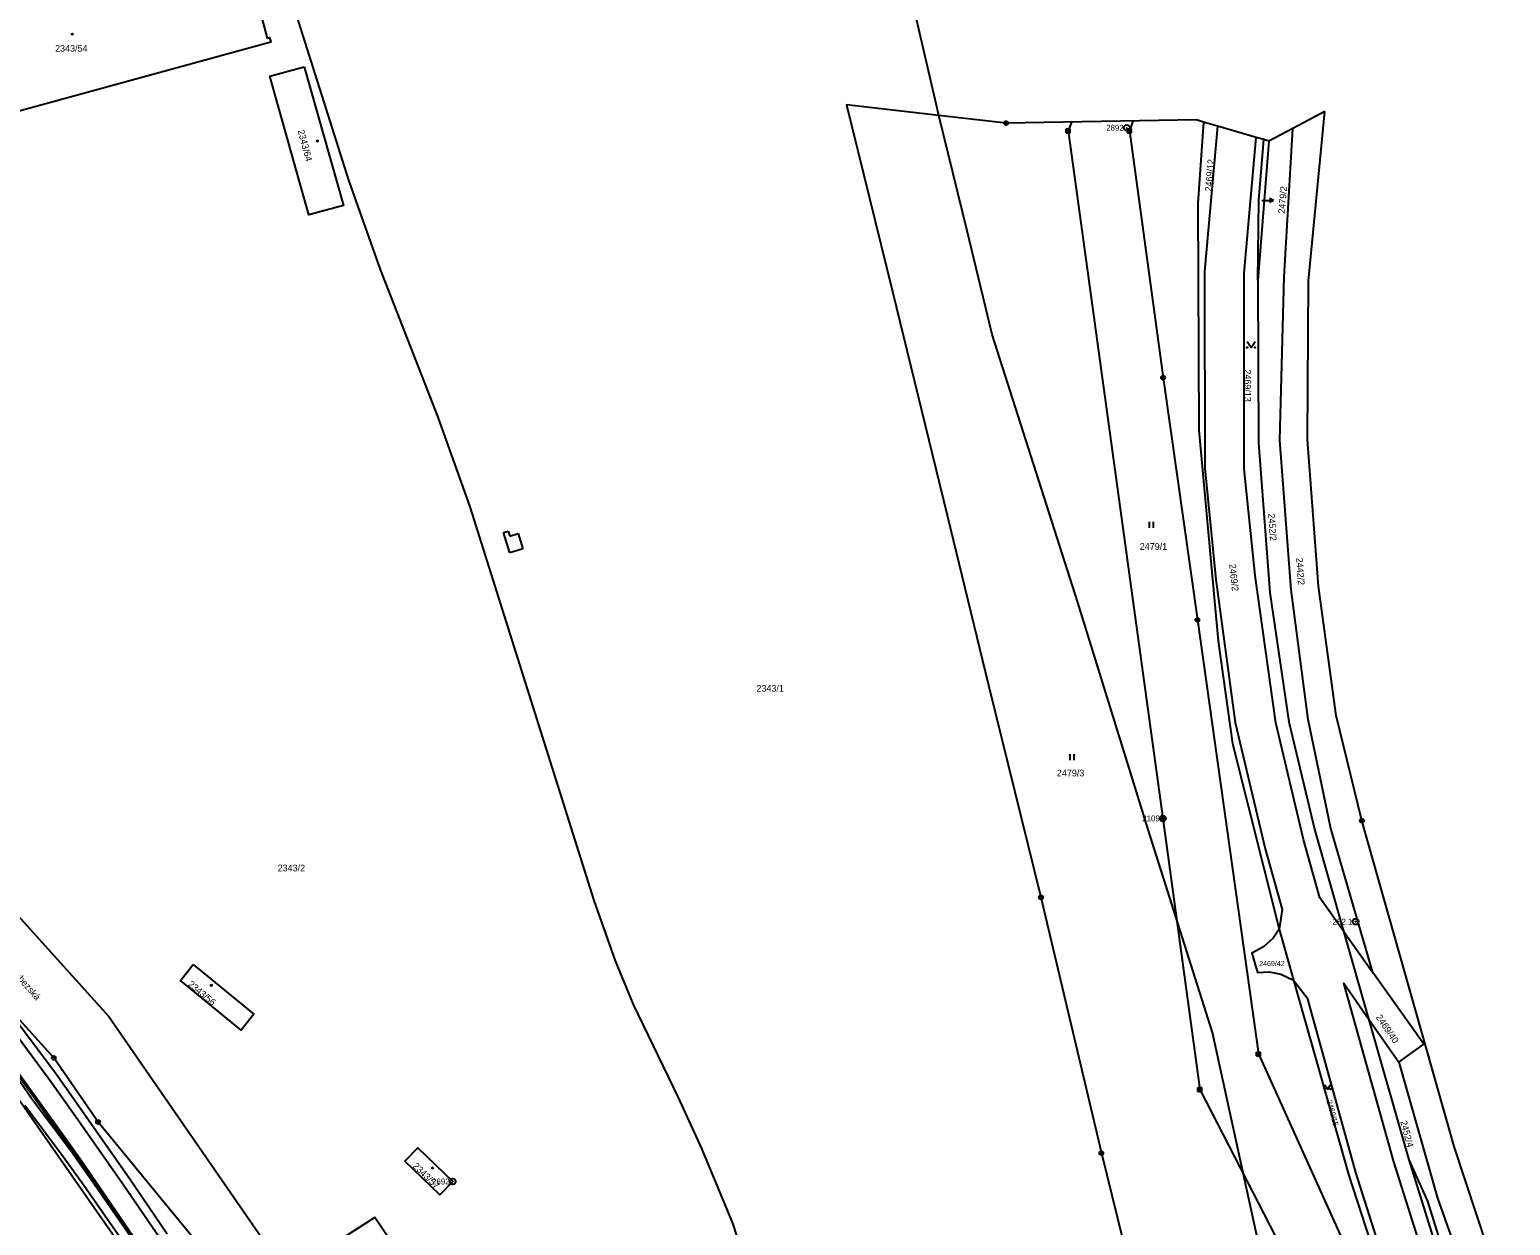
# Model space of a CAD drawing. Extents: x -821458 to -820266, y -1071458 to -1069826.
# Drawn here: x -820951.1 to -820575.5, y -1070854 to -1070550.7 of the extents above; entities that cross this region are included whole.
import ezdxf

# ---------------------------------------------------------------- set-up
doc = ezdxf.new("R2010")
doc.units = 0
for name, color, linetype in [('Vrstva 1', 7, 'Continuous'), ('Vrstva 13', 7, 'Continuous'), ('Vrstva 2', 7, 'Continuous'), ('Vrstva 3', 7, 'Continuous'), ('Vrstva 4', 7, 'Continuous'), ('Vrstva 5', 7, 'Continuous'), ('Vrstva 6', 7, 'Continuous'), ('Vrstva 7', 7, 'Continuous'), ('Vrstva 8', 7, 'Continuous')]:
    doc.layers.add(name, color=color, linetype=linetype)

msp = doc.modelspace()

# ---------------------------------------------------------------- linework, layer by layer
at = {"layer": 'Vrstva 1'}
for p, q in [((-820721.42, -1070568.42), (-820751, -1070439.83)), ((-820720.44, -1070572.46), (-820721.42, -1070568.42)), ((-820622.5, -1070571.49), (-820630.65, -1070575.77)), ((-820703.4, -1070574.43), (-820720.44, -1070572.46)), ((-820655.09, -1070573.64), (-820703.4, -1070574.43)), ((-820653.29, -1070574.2), (-820655.09, -1070573.64)), ((-820649.79, -1070575.18), (-820653.29, -1070574.2)), ((-820639.94, -1070578.04), (-820649.79, -1070575.18)), ((-820637.98, -1070578.61), (-820639.94, -1070578.04)), ((-820636.74, -1070578.97), (-820639.52, -1070614.28)), ((-820636.74, -1070578.97), (-820637.98, -1070578.61)), ((-820630.65, -1070575.77), (-820636.74, -1070578.97)), ((-820633.34, -1070773.88), (-820634.1, -1070778.9)), ((-820634.1, -1070778.9), (-820630.5, -1070791.8)), ((-820617.78, -1070779.43), (-820610.37, -1070789.85)), ((-820617.78, -1070779.43), (-820611.45, -1070801.61)), ((-820630.5, -1070791.8), (-820627.05, -1070796.31)), ((-820969.81, -1070799.27), (-820928.15, -1070858.94)), ((-820611.45, -1070801.61), (-820603.74, -1070812.61)), ((-820611.45, -1070801.61), (-820601.24, -1070837.38))]:
    msp.add_line(p, q, dxfattribs=at)
for points in [[(-820757.14, -1070921.43), (-820751.69, -1070918.45), (-820772.76, -1070853.45), (-820780.56, -1070834.55), (-820786.59, -1070821.38), (-820797.89, -1070798.01), (-820802.49, -1070786.9), (-820807.86, -1070771.6), (-820839.34, -1070671.73), (-820847.49, -1070649.05), (-820862.12, -1070611.55), (-820870.18, -1070588.9), (-820893.88, -1070513.71)], [(-820987.3, -1070553.53), (-820984.32, -1070553.15), (-820984.15, -1070553.64), (-820896.5, -1070529.65), (-820896.17, -1070530.88), (-820896.75, -1070531.03), (-820895.04, -1070537.38), (-820894.46, -1070537.22), (-820894.09, -1070538.61), (-820894.67, -1070538.77), (-820892.95, -1070545.12), (-820892.38, -1070544.96), (-820892, -1070546.35), (-820892.58, -1070546.51), (-820890.86, -1070552.89), (-820890.28, -1070552.73), (-820889.96, -1070553.93), (-820980.44, -1070578.68)], [(-820881.48, -1070560.15), (-820871.53, -1070595.32), (-820880.27, -1070597.68), (-820890.22, -1070562.51), (-820881.48, -1070560.15)], [(-820720.44, -1070572.46), (-820743.88, -1070569.76), (-820732.22, -1070617.16), (-820718.37, -1070673.87), (-820707.85, -1070716.96), (-820694.56, -1070770.81), (-820679.24, -1070835.68), (-820666.97, -1070885.51), (-820662.98, -1070891.79), (-820644.73, -1070894.66)], [(-820575.47, -1070877.31), (-820589.75, -1070833.98), (-820613.15, -1070751.36), (-820619.68, -1070724.73), (-820624.16, -1070691.86), (-820626.98, -1070654.7), (-820626.67, -1070614.41), (-820622.5, -1070571.49)], [(-820638.63, -1070895.3), (-820639, -1070860.06), (-820651.05, -1070805.08), (-820667.4, -1070753.6), (-820685.24, -1070696.04), (-820706.9, -1070628.02), (-820713.28, -1070601.74), (-820720.44, -1070572.46)], [(-820653.29, -1070574.2), (-820654.8, -1070594.7), (-820654.5, -1070652.3), (-820649.6, -1070705.8), (-820646, -1070731.8), (-820634.1, -1070778.9)], [(-820649.79, -1070575.18), (-820653.1, -1070612.1), (-820653, -1070661.95), (-820650.17, -1070690.23), (-820645.27, -1070726.49), (-820637.71, -1070758.5), (-820633.34, -1070773.88)], [(-820617.78, -1070779.43), (-820623.84, -1070770.91), (-820627.97, -1070756.18), (-820634.95, -1070726.51), (-820640.2, -1070689.19), (-820643, -1070662.1), (-820643, -1070612.5), (-820639.94, -1070578.04)], [(-820639.52, -1070614.28), (-820639.3, -1070594), (-820637.98, -1070578.61)], [(-820610.37, -1070789.85), (-820621.01, -1070753.33), (-820626.77, -1070725.67), (-820631.06, -1070692.78), (-820633.95, -1070654.83), (-820632.82, -1070613.38), (-820630.65, -1070575.77)], [(-821122.14, -1070589.18), (-821105.63, -1070607.47), (-821052.06, -1070666.88), (-820984.98, -1070741.28), (-820930.99, -1070801.01), (-820892.18, -1070857.22), (-820885.9, -1070866.32)], [(-820639.52, -1070614.28), (-820639.34, -1070655.55), (-820636.46, -1070693.5), (-820631.68, -1070726.33), (-820625.08, -1070753.87), (-820617.78, -1070779.43)], [(-820830.48, -1070974.59), (-820860.94, -1070928.75), (-820897.16, -1070874.24), (-820903.48, -1070864.73), (-820933.76, -1070827.81), (-820944.98, -1070811.53), (-820977.14, -1070776.05), (-821034.82, -1070708.07), (-821038.73, -1070703.46), (-821059.1, -1070680.77), (-821064.12, -1070689.43)], [(-820634.1, -1070778.9), (-820635.67, -1070781.21), (-820638.11, -1070783.39)], [(-820638.11, -1070783.39), (-820641.03, -1070784.97), (-820639.65, -1070789.87), (-820636.63, -1070789.7)], [(-820909.62, -1070787.86), (-820894.2, -1070800.43), (-820897.46, -1070804.5), (-820912.83, -1070791.87), (-820909.62, -1070787.86)], [(-820636.63, -1070789.7), (-820633.7, -1070790.28), (-820630.5, -1070791.8)], [(-820630.5, -1070791.8), (-820616.42, -1070841.34), (-820608.96, -1070864.52)], [(-820591.18, -1070881.76), (-820605.01, -1070837.88), (-820617.76, -1070792.61), (-820611.45, -1070801.61)], [(-820603.74, -1070812.61), (-820597.44, -1070808.04), (-820610.37, -1070789.85)], [(-820627.05, -1070796.31), (-820614.77, -1070840.62), (-820600.74, -1070884.82), (-820599.23, -1070892.6)], [(-820603.74, -1070812.61), (-820594, -1070847.1), (-820579.4, -1070888.1)], [(-820855.92, -1070837.73), (-820852.62, -1070834.37), (-820843.79, -1070842.89), (-820847.05, -1070846.25), (-820855.92, -1070837.73)], [(-820601.24, -1070837.38), (-820587.25, -1070882.1), (-820583.95, -1070890.7)], [(-820847.86, -1070875.03), (-820857.84, -1070860.4), (-820863.58, -1070851.99), (-820885.4, -1070866), (-820885.9, -1070866.32)]]:
    msp.add_lwpolyline(points, dxfattribs=at)
at = {"layer": 'Vrstva 13'}
msp.add_lwpolyline([(-820904.89, -1070889.85), (-820906.75, -1070887.02), (-820915.84, -1070872.29), (-820921.1, -1070864.54), (-820924.16, -1070858.76), (-820935.49, -1070842.47), (-820940.7, -1070835.15), (-820950.45, -1070822.13), (-820960.57, -1070807.59), (-820967.99, -1070796.51), (-820968.45, -1070795.86), (-820964.16, -1070792.35), (-820957.12, -1070802.08), (-820946.13, -1070816.91), (-820939.51, -1070826.31), (-820927.43, -1070843.51), (-820917.95, -1070857.45), (-820910.17, -1070868.83), (-820902.77, -1070879.51), (-820898.51, -1070886.1), (-820899.32, -1070886.63)], close=True, dxfattribs=at)
for points in [[(-820916.21, -1070856.27), (-820925.69, -1070842.31), (-820937.79, -1070825.09), (-820944.42, -1070815.67), (-820955.42, -1070800.84)], [(-820924.84, -1070856.86), (-820937.9, -1070837.8), (-820944.15, -1070829.04), (-820956.36, -1070812.01)], [(-820956.64, -1070812.21), (-820944.43, -1070829.24), (-820938.14, -1070838.08), (-820925.14, -1070857.05)], [(-820952.33, -1070823.49), (-820942.57, -1070836.51), (-820937.39, -1070843.81), (-820926.14, -1070859.96), (-820923.08, -1070865.74), (-820917.78, -1070873.55), (-820908.71, -1070888.26), (-820906.28, -1070891.93), (-820900.9, -1070899.97), (-820897.17, -1070905.83), (-820879.17, -1070932.66), (-820864.17, -1070956.47), (-820859.08, -1070965.49), (-820854.56, -1070972.59), (-820849.07, -1070982.53), (-820847.11, -1070985.26), (-820846.8, -1070985.75)]]:
    msp.add_lwpolyline(points, dxfattribs=at)
at = {"layer": 'Vrstva 3'}
for p, q in [((-820667.01, -1070677.1), (-820667.01, -1070675.6)), ((-820666.01, -1070677.1), (-820666.01, -1070675.6)), ((-820687.12, -1070736), (-820687.12, -1070734.5)), ((-820686.12, -1070736), (-820686.12, -1070734.5))]:
    msp.add_line(p, q, dxfattribs=at)
for points in [[(-820642.25, -1070629.85), (-820641.25, -1070631.35), (-820640.25, -1070629.85)], [(-820622.5, -1070818.41), (-820621.8, -1070819.46), (-820621.1, -1070818.41)]]:
    msp.add_lwpolyline(points, dxfattribs=at)
for centre, radius in [((-820642.25, -1070631.35), 0.1), ((-820640.25, -1070631.35), 0.1), ((-820622.5, -1070819.46), 0.07), ((-820621.1, -1070819.46), 0.07)]:
    msp.add_circle(centre, radius, dxfattribs=at)
at = {"layer": 'Vrstva 4'}
for p, q in [((-820830.9, -1070678.29), (-820829.73, -1070677.93)), ((-820829.28, -1070683.43), (-820830.9, -1070678.29)), ((-820829.73, -1070677.93), (-820829.33, -1070679.21)), ((-820829.33, -1070679.21), (-820827.2, -1070678.55)), ((-820827.2, -1070678.55), (-820826.01, -1070682.4)), ((-820826.01, -1070682.4), (-820829.28, -1070683.43)), ((-820601.24, -1070837.38), (-820596.5, -1070847.9)), ((-820596.5, -1070847.9), (-820588, -1070875.3))]:
    msp.add_line(p, q, dxfattribs=at)
at = {"layer": 'Vrstva 5'}
for centre in [(-820940.28, -1070551.87), (-820878.09, -1070578.99), (-820905.02, -1070793.17), (-820848.91, -1070839.43)]:
    msp.add_circle(centre, 0.175, dxfattribs=at)
at = {"layer": 'Vrstva 6'}
for p, q in [((-820686.78, -1070574.16), (-820687.67, -1070576.42)), ((-820671.21, -1070573.9), (-820672.06, -1070576.41)), ((-820688.17, -1070575.92), (-820687.17, -1070575.92)), ((-820688.17, -1070576.92), (-820688.17, -1070575.92)), ((-820688.17, -1070576.12), (-820687.17, -1070576.12)), ((-820688.17, -1070576.32), (-820687.17, -1070576.32)), ((-820688.17, -1070576.52), (-820687.17, -1070576.52)), ((-820688.17, -1070576.72), (-820687.17, -1070576.72)), ((-820688.17, -1070576.92), (-820687.17, -1070576.92)), ((-820687.97, -1070576.92), (-820687.97, -1070575.92)), ((-820687.77, -1070576.92), (-820687.77, -1070575.92)), ((-820687.67, -1070576.42), (-820663.62, -1070750.8)), ((-820687.57, -1070576.92), (-820687.57, -1070575.92)), ((-820687.37, -1070576.92), (-820687.37, -1070575.92)), ((-820687.17, -1070576.92), (-820687.17, -1070575.92)), ((-820672.56, -1070575.91), (-820671.56, -1070575.91)), ((-820672.56, -1070576.91), (-820672.56, -1070575.91)), ((-820672.56, -1070576.11), (-820671.56, -1070576.11)), ((-820672.56, -1070576.31), (-820671.56, -1070576.31)), ((-820672.56, -1070576.51), (-820671.56, -1070576.51)), ((-820672.56, -1070576.71), (-820671.56, -1070576.71)), ((-820672.56, -1070576.91), (-820671.56, -1070576.91)), ((-820672.36, -1070576.91), (-820672.36, -1070575.91)), ((-820672.16, -1070576.91), (-820672.16, -1070575.91)), ((-820672.06, -1070576.41), (-820663.57, -1070639)), ((-820671.96, -1070576.91), (-820671.96, -1070575.91)), ((-820671.76, -1070576.91), (-820671.76, -1070575.91)), ((-820671.56, -1070576.91), (-820671.56, -1070575.91)), ((-820663.57, -1070639), (-820654.85, -1070700.44)), ((-820654.85, -1070700.44), (-820639.4, -1070810.55)), ((-820664.12, -1070750.3), (-820663.12, -1070750.3)), ((-820664.12, -1070751.3), (-820664.12, -1070750.3)), ((-820664.12, -1070750.5), (-820663.12, -1070750.5)), ((-820664.12, -1070750.7), (-820663.12, -1070750.7)), ((-820664.12, -1070750.9), (-820663.12, -1070750.9)), ((-820664.12, -1070751.1), (-820663.12, -1070751.1)), ((-820664.12, -1070751.3), (-820663.12, -1070751.3)), ((-820663.92, -1070751.3), (-820663.92, -1070750.3)), ((-820663.72, -1070751.3), (-820663.72, -1070750.3)), ((-820663.62, -1070750.8), (-820654.22, -1070819.58)), ((-820663.52, -1070751.3), (-820663.52, -1070750.3)), ((-820663.32, -1070751.3), (-820663.32, -1070750.3)), ((-820663.12, -1070751.3), (-820663.12, -1070750.3)), ((-820639.9, -1070810.05), (-820638.9, -1070810.05)), ((-820639.9, -1070811.05), (-820639.9, -1070810.05)), ((-820639.9, -1070810.25), (-820638.9, -1070810.25)), ((-820639.9, -1070810.45), (-820638.9, -1070810.45)), ((-820639.9, -1070810.65), (-820638.9, -1070810.65)), ((-820639.9, -1070810.85), (-820638.9, -1070810.85)), ((-820639.9, -1070811.05), (-820638.9, -1070811.05)), ((-820639.7, -1070811.05), (-820639.7, -1070810.05)), ((-820639.5, -1070811.05), (-820639.5, -1070810.05)), ((-820639.4, -1070810.55), (-820597.93, -1070902.2)), ((-820639.3, -1070811.05), (-820639.3, -1070810.05)), ((-820639.1, -1070811.05), (-820639.1, -1070810.05)), ((-820638.9, -1070811.05), (-820638.9, -1070810.05)), ((-820654.72, -1070819.08), (-820653.72, -1070819.08)), ((-820654.72, -1070820.08), (-820654.72, -1070819.08)), ((-820654.72, -1070819.28), (-820653.72, -1070819.28)), ((-820654.72, -1070819.48), (-820653.72, -1070819.48)), ((-820654.52, -1070820.08), (-820654.52, -1070819.08)), ((-820654.32, -1070820.08), (-820654.32, -1070819.08)), ((-820654.22, -1070819.58), (-820611.27, -1070902.97)), ((-820654.12, -1070820.08), (-820654.12, -1070819.08)), ((-820653.92, -1070820.08), (-820653.92, -1070819.08)), ((-820653.72, -1070820.08), (-820653.72, -1070819.08)), ((-820654.72, -1070819.68), (-820653.72, -1070819.68)), ((-820654.72, -1070819.88), (-820653.72, -1070819.88)), ((-820654.72, -1070820.08), (-820653.72, -1070820.08))]:
    msp.add_line(p, q, dxfattribs=at)
for centre, radius in [((-820663.57, -1070639), 0.5), ((-820663.57, -1070639), 0.4), ((-820663.57, -1070639), 0.3), ((-820663.57, -1070639), 0.2), ((-820663.57, -1070639), 0.1), ((-820654.85, -1070700.44), 0.5), ((-820654.85, -1070700.44), 0.4), ((-820654.85, -1070700.44), 0.3), ((-820654.85, -1070700.44), 0.2), ((-820654.85, -1070700.44), 0.1)]:
    msp.add_circle(centre, radius, dxfattribs=at)
at = {"layer": 'Vrstva 7'}
for p, q in [((-820638.56, -1070594.09), (-820635.56, -1070594.04)), ((-820635.56, -1070594.04), (-820636.57, -1070593.55)), ((-820635.56, -1070594.04), (-820636.55, -1070594.56))]:
    msp.add_line(p, q, dxfattribs=at)
at = {"layer": 'Vrstva 8'}
for centre, radius in [((-820703.4, -1070574.43), 0.5), ((-820703.4, -1070574.43), 0.0303), ((-820672.78, -1070575.62), 0.75), ((-820672.78, -1070575.62), 0.03), ((-820663.62, -1070750.8), 0.75), ((-820663.62, -1070750.8), 0.03), ((-820613.15, -1070751.36), 0.5), ((-820613.15, -1070751.36), 0.0303), ((-820694.56, -1070770.81), 0.5), ((-820694.56, -1070770.81), 0.0303), ((-820614.74, -1070776.98), 0.75), ((-820614.74, -1070776.98), 0.03), ((-820944.98, -1070811.53), 0.5), ((-820944.98, -1070811.53), 0.0303), ((-820933.76, -1070827.81), 0.5), ((-820933.76, -1070827.81), 0.0303), ((-820679.24, -1070835.68), 0.5), ((-820679.24, -1070835.68), 0.0303), ((-820843.79, -1070842.89), 0.75), ((-820843.79, -1070842.89), 0.03)]:
    msp.add_circle(centre, radius, dxfattribs=at)

# ---------------------------------------------------------------- texts
at = {"layer": 'Vrstva 2'}
for s, height, p in [('2343/54', 1.7, (-820944.65, -1070556.32)), ('2479/1', 1.7, (-820669.49, -1070682.67)), ('2343/1', 1.7, (-820766.73, -1070718.64)), ('2479/3', 1.7, (-820690.52, -1070740.14)), ('2343/2', 1.7, (-820888.19, -1070764.21)), ('2469/42', 1.3, (-820639.21, -1070788.26))]:
    msp.add_text(s, height=height, dxfattribs=at).set_placement(p)
for s, height, rotation, p in [('2343/64', 1.7, 285, (-820883.12, -1070576.34)), ('2469/12', 1.7, 85, (-820651.27, -1070591.84)), ('2479/2', 1.7, 85, (-820632.7, -1070597.47)), ('2469/13', 1.7, 270, (-820642.95, -1070636.91)), ('2452/2', 1.7, 274, (-820636.93, -1070673.51)), ('2469/2', 1.7, 276, (-820646.81, -1070686.31)), ('2442/2', 1.7, 274, (-820629.81, -1070684.73)), ('2343/56', 1.7, 320, (-820911.08, -1070793.12)), ('2469/40', 1.7, 304, (-820609.68, -1070801.23)), ('2469/15', 1.4, 285, (-820622.12, -1070822.43)), ('2452/4', 1.7, 285, (-820603.41, -1070827.68)), ('2343/57', 1.7, 316, (-820854.04, -1070839.18))]:
    msp.add_text(s, height=height, rotation=rotation, dxfattribs=at).set_placement(p)
at = {"layer": 'Vrstva 7'}
msp.add_text('Lobezská', height=1.7, rotation=311, dxfattribs=at).set_placement((-820955.86, -1070789.71))
at = {"layer": 'Vrstva 8'}
for s, p in [('2892', (-820678.03, -1070576.37)), ('2109', (-820668.87, -1070751.55)), ('252.1', (-820620.56, -1070777.73)), ('2692', (-820849.04, -1070843.64))]:
    msp.add_text(s, height=1.5, dxfattribs=at).set_placement(p)

doc.saveas('drawing.dxf')
